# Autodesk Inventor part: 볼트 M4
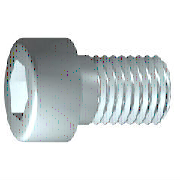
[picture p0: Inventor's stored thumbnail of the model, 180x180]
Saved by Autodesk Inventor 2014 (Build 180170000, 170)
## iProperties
Created: 2018-09
Part Number: 볼트 M4
Material: 스테인리스강
Description: 6각머리 태핑 나사
Document SubType Name: Modeling
Standard: KS B 1003
Standards Organization: KS
Language: ko-KR
Size Designation: M 4 x 10
Categories: <MemberInstance><Categories><Category DisplayName="조임쇠" InternalName="e4da775c-781d-43d5-af7c-5136215cf5a6" Mnemonic="FSTN"><Category DisplayName="볼트" InternalN
Density: 8.08 g/cm^3
Appearance: 반광택
Mass: 2.09412 g
Surface Area: 3.0572 cm^2
Volume: 0.259174 cm^3
IsCustomPart: 0
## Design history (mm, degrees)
sketch "스케치1"
  geometry: L1 (-1, 0)-(10, 0); L2 (10, 0)-(10, 2); L3 (10, 2)-(1.75, 2); L4 (1.75, 2)-(1.32, 2); L5 (1.32, 2)-(0, 2); L6 (0, 2)-(0, 3.5); L7 (0, 3.5)-(-4, 3.5); L8 (-4, 3.5)-(-4, 1.732); L9 (-4, 1.732)-(-2, 1.732); L10 (-2, 1.732)-(-1, 0); L11 (-6.8, 0)-(12.8, 0) reference; L12 (0, -0.7)-(0, 4.2) reference; L13 (1.75, 2)-(0, 2)
  constraints: 22 end point, 6 parallel, 2 collinear, 2 perpendicular, 1 horizontal, 1 point on line
  dimensions: "d1" = 8.25 distance from line of L3.end L2 (= GEL); "d2" = 0.42952 distance of L4.end L3.end (computed from GAL); "d3" = 4 distance between parallel lines of L8 L6 (= KOH); "d4" = 2 distance of L8.end L9.end (= INTI); "d5" = 60 deg angle of L10 L1; "d6" = 4 diameter of L3 L1 (= GD); "d7" = 4 diameter of L5 L1 (= BDM); "d8" = 3.4641 diameter of L9 L1 (= 1.1547 x SW); "d9" = 7 diameter of L7 L1 (= KOD); "d26" = 10 distance between parallel lines of L12 L2 (= NLG)
revolve "본체" sketch "스케치1" stored, may be unused: angle "d10" = 90 deg
sketch "스케치2"
  geometry: L1 (0, -4.9)-(0, 4.9) reference; L2 (-4.9, 0)-(4.9, 0) reference; L3 (1.732, 0)-(0.866, -1.5); L4 (0.866, -1.5)-(-0.866, -1.5); L5 (-0.866, -1.5)-(-1.732, 0); L6 (-1.732, 0)-(-0.866, 1.5); L7 (-0.866, 1.5)-(0.866, 1.5); L8 (0.866, 1.5)-(1.732, 0); 2 further points
  constraints: 12 end point, 1 coincident, 1 horizontal alignment, 1 point on line, 12 other
extrude "슬롯" join sketch "스케치2" stored distance "d11" = 10; taper "d12" = 0 deg
workplane "Work Plane1"
fillet "Fillet2" dims "d30" = 0.1 (= R)
body "Solid1"
fillet "모깎기1" dims "d17" = 0.4 (= RR)
feature "스레드" dims "d13" = 8.25 (= GEL), "d14" = 0
chamfer "모따기1" distance "d15" = 0.42941 (= -0.5 x SPD + 0.5 x GD); stored, may be unused: second distance "d16" = 0.42941 (= GUL), angle "d27" = 45 deg
other parameters: "GD" = 4 (= NND) [user parameter; used in 2 equation terms], "NLG" = 10 [user parameter; used in 1 equation term], "GEL" = 8.25 [user parameter; used in 2 equation terms], "KOD" = 7 [user parameter; used in 1 equation term], "KOH" = 4 [user parameter; used in 1 equation term], "INTI" = 2 [user parameter; used in 1 equation term], "GAL" = 0.42941 (= 0.61345 x PTC) [user parameter; used in 1 equation term], "GUL" = 0.42941 (= 0.61345 x PTC) [user parameter; used in 1 equation term], "BDM" = 4 (= NND) [user parameter; used in 1 equation term], "SW" = 3 [user parameter; used in 2 equation terms], "RR" = 0.4 [user parameter; used in 1 equation term], "SPD" = 3.14117 (= NND - 1.2269 x PTC) [user parameter; used in 1 equation term], "d19" = 0, "d28" = 0, "d29" = 0, "R" = 0.1 [user parameter; used in 1 equation term], "PHH" = 0.2 [user parameter], "GD1" = 3.14117 (= THREADDIA - 1.2269 x PTC) [user parameter], "THREADDIA" = 4 [user parameter; used in 1 equation term], "FAWI" = 45 deg [user parameter], "TPU" = 14.28571 (computed from PTC) [user parameter], "PTC" = 0.7 [user parameter; used in 5 equation terms], "NND" = 4 [user parameter; used in 3 equation terms], "TOA" = 30 deg [user parameter], "E0" = 3.465 (= 1.155 x SW) [user parameter]
